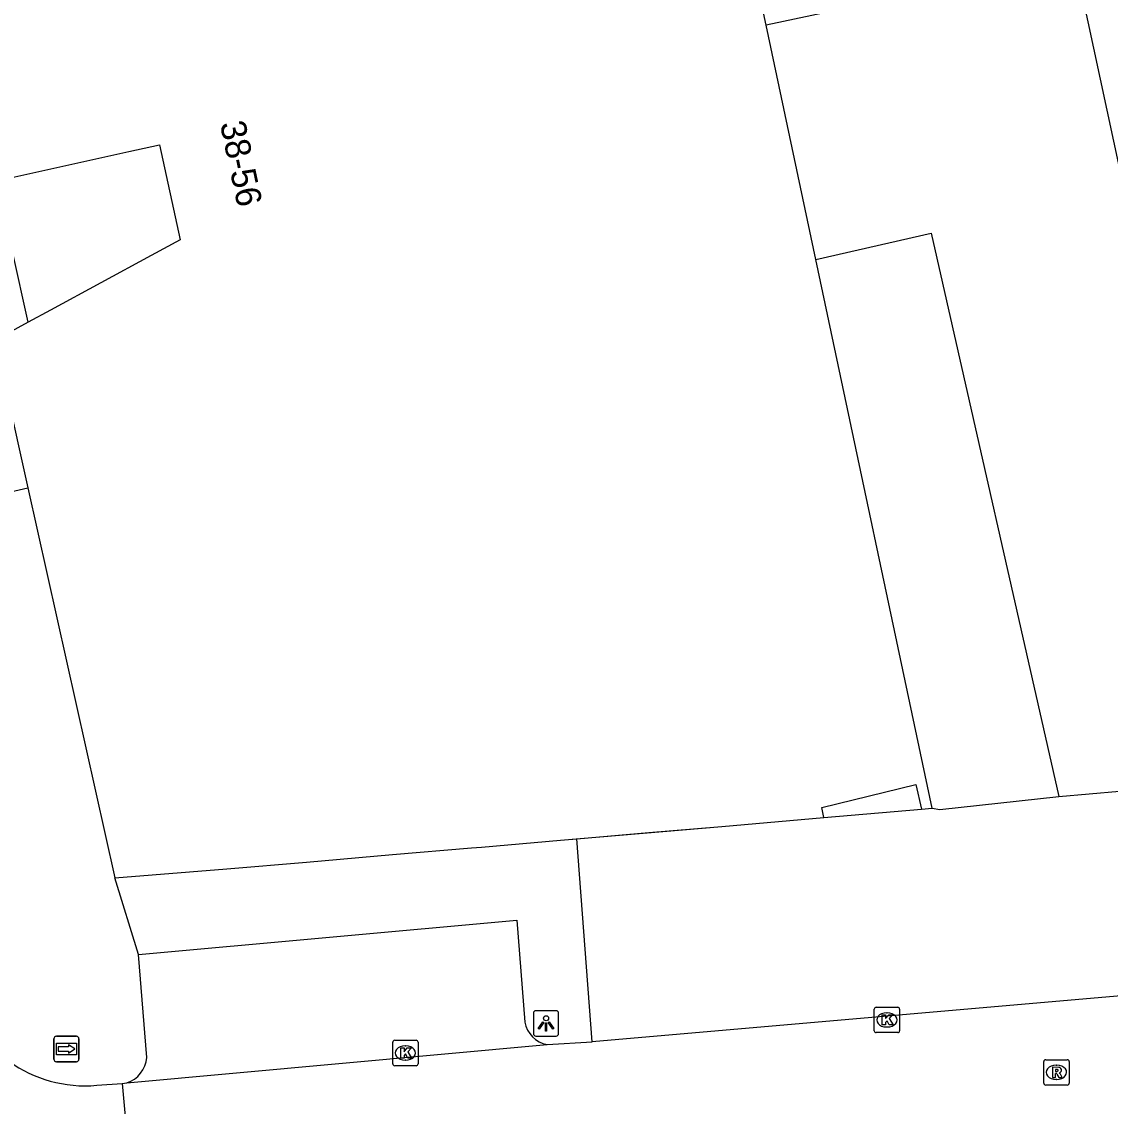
# Model space of a CAD drawing. Extents: x 160557 to 161245, y 385330 to 386505.
# Drawn here: x 160808.55 to 160851.48, y 385607.11 to 385649.87 of the extents above; entities that cross this region are included whole.
import ezdxf

# ---------------------------------------------------------------- set-up
doc = ezdxf.new("R2010")
doc.units = 0
for name, color, linetype in [('IMGEO_Kolk', 7, 'Continuous'), ('IMGEO_Lichtpunt', 7, 'Continuous'), ('IMGEO_Pand', 7, 'Continuous'), ('IMGEO_Pand_nummerreeks', 7, 'Continuous'), ('IMGEO_Pand_overbouw', 7, 'Continuous'), ('IMGEO_Parkeervlak_open', 7, 'Continuous'), ('IMGEO_Rijbaan_lokaal_open', 7, 'Continuous'), ('IMGEO_Rioolput', 7, 'Continuous'), ('IMGEO_Voetpad_gesloten', 7, 'Continuous'), ('IMGEO_Voetpad_open', 7, 'Continuous'), ('IMGEO_Wegwijzer', 7, 'Continuous')]:
    doc.layers.add(name, color=color, linetype=linetype)

msp = doc.modelspace()

# ---------------------------------------------------------------- linework, layer by layer
at = {"layer": 'IMGEO_Kolk'}
for p, q in [((160842.172, 385610.091), (160842.172, 385610.943)), ((160842.247, 385611.017), (160843.099, 385611.017)), ((160842.66, 385610.797), (160842.685, 385610.797)), ((160843.173, 385610.943), (160843.173, 385610.091)), ((160843.099, 385610.017), (160842.247, 385610.017)), ((160842.683, 385610.237), (160842.658, 385610.237)), ((160823.186, 385608.786), (160823.186, 385609.638)), ((160823.261, 385609.712), (160824.113, 385609.712)), ((160823.674, 385609.492), (160823.699, 385609.492)), ((160824.187, 385609.638), (160824.187, 385608.786)), ((160824.113, 385608.712), (160823.261, 385608.712)), ((160823.697, 385608.932), (160823.672, 385608.932))]:
    msp.add_line(p, q, dxfattribs=at)
for points in [[(160842.172, 385610.091), (160842.172, 385610.943)], [(160842.247, 385611.017), (160843.099, 385611.017)], [(160843.173, 385610.943), (160843.173, 385610.091)], [(160842.493, 385610.717), (160842.616, 385610.717), (160842.616, 385610.566), (160842.746, 385610.717), (160842.91, 385610.717), (160842.764, 385610.566), (160842.917, 385610.317), (160842.765, 385610.317), (160842.68, 385610.481), (160842.616, 385610.414), (160842.616, 385610.317), (160842.493, 385610.317), (160842.493, 385610.717)], [(160843.099, 385610.017), (160842.247, 385610.017)], [(160823.186, 385608.786), (160823.186, 385609.638)], [(160823.261, 385609.712), (160824.113, 385609.712)], [(160824.187, 385609.638), (160824.187, 385608.786)], [(160823.507, 385609.412), (160823.63, 385609.412), (160823.63, 385609.261), (160823.76, 385609.412), (160823.924, 385609.412), (160823.778, 385609.261), (160823.931, 385609.012), (160823.779, 385609.012), (160823.694, 385609.176), (160823.63, 385609.109), (160823.63, 385609.012), (160823.507, 385609.012), (160823.507, 385609.412)], [(160824.113, 385608.712), (160823.261, 385608.712)]]:
    msp.add_lwpolyline(points, dxfattribs=at)
for centre, start, end in [((160842.249, 385610.941), 91.552, 178.448), ((160842.249, 385610.941), 91.552, 178.448), ((160843.097, 385610.941), 1.552, 88.448), ((160843.097, 385610.941), 1.552, 88.448), ((160842.249, 385610.093), 181.552, 268.448), ((160842.249, 385610.093), 181.552, 268.448), ((160843.097, 385610.093), 271.552, 358.448), ((160843.097, 385610.093), 271.552, 358.448), ((160823.263, 385609.636), 91.552, 178.448), ((160823.263, 385609.636), 91.552, 178.448), ((160824.111, 385609.636), 1.552, 88.448), ((160824.111, 385609.636), 1.552, 88.448), ((160823.263, 385608.788), 181.552, 268.448), ((160823.263, 385608.788), 181.552, 268.448), ((160824.111, 385608.788), 271.552, 358.448), ((160824.111, 385608.788), 271.552, 358.448)]:
    msp.add_arc(centre, 0.0765, start, end, dxfattribs=at)
for centre, major_axis, ratio, start_param, end_param in [((160842.659, 385610.517), (-0.387, 0.002), 0.722429, 4.712389, 7.853982), ((160842.684, 385610.517), (-0.39, 0.002), 0.717154, 1.570796, 4.712389), ((160823.673, 385609.212), (-0.387, 0.002), 0.722429, 4.712389, 7.853982), ((160823.698, 385609.212), (-0.39, 0.002), 0.717154, 1.570796, 4.712389)]:
    msp.add_ellipse(centre, major_axis=major_axis, ratio=ratio, start_param=start_param, end_param=end_param, dxfattribs=at)
at = {"layer": 'IMGEO_Lichtpunt'}
for p, q in [((160828.732, 385610.783), (160828.732, 385609.976)), ((160828.732, 385610.783), (160828.732, 385609.976)), ((160829.634, 385610.878), (160828.826, 385610.878)), ((160829.634, 385610.878), (160828.826, 385610.878)), ((160829.728, 385609.976), (160829.728, 385610.783)), ((160829.728, 385609.976), (160829.728, 385610.783)), ((160828.826, 385609.882), (160829.634, 385609.882)), ((160828.826, 385609.882), (160829.634, 385609.882))]:
    msp.add_line(p, q, dxfattribs=at)
for points in [[(160829.106, 385610.447), (160829.145, 385610.419), (160828.957, 385610.157), (160828.919, 385610.184), (160829.106, 385610.447)], [(160829.208, 385610.399), (160829.255, 385610.399), (160829.255, 385610.077), (160829.208, 385610.077), (160829.208, 385610.399)], [(160829.318, 385610.419), (160829.356, 385610.446), (160829.543, 385610.184), (160829.504, 385610.156), (160829.318, 385610.419)]]:
    msp.add_lwpolyline(points, dxfattribs=at)
msp.add_circle((160829.231, 385610.581), 0.0994, dxfattribs=at)
for centre, start, end in [((160828.826, 385610.783), 90, 180), ((160828.826, 385610.783), 90, 180), ((160829.634, 385610.783), 0, 90), ((160829.634, 385610.783), 0, 90), ((160828.826, 385609.976), 180, 270), ((160828.826, 385609.976), 180, 270), ((160829.634, 385609.976), 270, 0), ((160829.634, 385609.976), 270, 360)]:
    msp.add_arc(centre, 0.0946, start, end, dxfattribs=at)
at = {"layer": 'IMGEO_Pand'}
for points in [[(160837.913, 385649.731), (160831.957, 385677.464)], [(160882.614, 385635.957), (160878.759, 385636.941), (160867.447, 385640.094), (160867.321, 385639.572), (160859.358, 385637.818), (160858.199, 385643.077), (160852.372, 385641.675), (160850.09, 385652.328), (160837.913, 385649.731)], [(160839.871, 385640.501), (160837.913, 385649.731)], [(160807.556, 385643.592), (160808.287, 385643.755), (160812.781, 385644.753), (160813.993, 385645.022), (160814.797, 385641.265), (160813.659, 385640.65), (160809.682, 385638.499), (160808.802, 385638.023)], [(160844.463, 385618.859), (160839.871, 385640.501)], [(160808.802, 385638.023), (160807.57, 385637.357)], [(160807.57, 385637.357), (160806.691, 385636.881), (160807.944, 385631.298), (160808.794, 385631.497), (160812.22, 385616.114)], [(160840.182, 385618.492), (160840.111, 385618.885), (160843.815, 385619.802), (160844.032, 385618.825)], [(160830.449, 385617.656), (160833.286, 385617.9), (160836.165, 385618.147), (160839.297, 385618.416), (160840.182, 385618.492)], [(160844.032, 385618.825), (160844.463, 385618.859)], [(160812.22, 385616.114), (160816.636, 385616.471), (160819.784, 385616.741), (160823.172, 385617.032), (160826.291, 385617.299), (160826.681, 385617.333), (160829.796, 385617.6), (160830.449, 385617.656)]]:
    msp.add_lwpolyline(points, dxfattribs=at)
at = {"layer": 'IMGEO_Pand_overbouw'}
msp.add_lwpolyline([(160800.168, 385670.228), (160806.16, 385643.282), (160808.794, 385631.497), (160812.22, 385616.114), (160816.636, 385616.471), (160819.784, 385616.741), (160823.172, 385617.032), (160826.291, 385617.299), (160826.681, 385617.333), (160829.796, 385617.6), (160836.165, 385618.147), (160839.297, 385618.416), (160840.182, 385618.492), (160844.032, 385618.825), (160844.463, 385618.859), (160839.871, 385640.501), (160837.913, 385649.731), (160831.957, 385677.464)], dxfattribs=at)
at = {"layer": 'IMGEO_Parkeervlak_open'}
msp.add_lwpolyline([(160839.871, 385640.501), (160844.423, 385641.532), (160849.453, 385619.331)], dxfattribs=at)
at = {"layer": 'IMGEO_Rijbaan_lokaal_open'}
for points in [[(160852.666, 385611.53), (160831.052, 385609.652)], [(160812.695, 385608.034), (160829.274, 385609.552)], [(160829.274, 385609.552), (160831.052, 385609.652)], [(160811.51, 385607.939), (160812.515, 385608.009)], [(160812.515, 385608.009), (160812.695, 385608.034)], [(160812.515, 385608.009), (160812.984, 385602.775)]]:
    msp.add_lwpolyline(points, dxfattribs=at)
msp.add_arc((160811.056, 385613.052), 5.134, 193.7305, 275.0747, dxfattribs=at)
at = {"layer": 'IMGEO_Rioolput'}
for p, q in [((160848.861, 385608.022), (160848.861, 385608.874)), ((160848.936, 385608.948), (160849.788, 385608.948)), ((160849.349, 385608.728), (160849.374, 385608.728)), ((160849.862, 385608.874), (160849.862, 385608.022)), ((160849.788, 385607.948), (160848.936, 385607.948)), ((160849.372, 385608.168), (160849.347, 385608.168))]:
    msp.add_line(p, q, dxfattribs=at)
for points in [[(160848.861, 385608.022), (160848.861, 385608.874)], [(160848.936, 385608.948), (160849.788, 385608.948)], [(160849.45, 385608.646), (160849.198, 385608.648), (160849.198, 385608.248)], [(160849.862, 385608.874), (160849.862, 385608.022)], [(160849.198, 385608.248), (160849.322, 385608.248), (160849.322, 385608.41), (160849.333, 385608.41)], [(160849.376, 385608.567), (160849.322, 385608.567), (160849.322, 385608.486)], [(160849.322, 385608.486), (160849.374, 385608.486)], [(160849.38, 385608.381), (160849.451, 385608.248), (160849.591, 385608.248), (160849.526, 385608.374)], [(160849.788, 385607.948), (160848.936, 385607.948)]]:
    msp.add_lwpolyline(points, dxfattribs=at)
for centre, radius, start, end in [((160848.938, 385608.872), 0.0765, 91.552, 178.448), ((160848.938, 385608.872), 0.0765, 91.552, 178.448), ((160849.449, 385608.536), 0.109, 350.3612, 89.416), ((160849.786, 385608.872), 0.0765, 1.552, 88.448), ((160849.786, 385608.872), 0.0765, 1.552, 88.448), ((160849.332, 385608.357), 0.0533, 26.0293, 88.6989), ((160849.358, 385608.675), 0.19, 274.7715, 282.9687), ((160849.382, 385608.471), 0.0964, 77.0061, 93.1865), ((160849.396, 385608.528), 0.0378, 276.6634, 79.6772), ((160849.447, 385608.536), 0.112, 277.5842, 350.9817), ((160849.431, 385608.321), 0.108, 29.5134, 73.7905), ((160848.938, 385608.024), 0.0765, 181.552, 268.448), ((160848.938, 385608.024), 0.0765, 181.552, 268.448), ((160849.786, 385608.024), 0.0765, 271.552, 358.448), ((160849.786, 385608.024), 0.0765, 271.552, 358.448)]:
    msp.add_arc(centre, radius, start, end, dxfattribs=at)
for centre, major_axis, ratio, start_param, end_param in [((160849.348, 385608.448), (-0.387, 0.002), 0.722429, 4.712389, 7.853982), ((160849.373, 385608.448), (-0.39, 0.002), 0.717154, 1.570796, 4.712389)]:
    msp.add_ellipse(centre, major_axis=major_axis, ratio=ratio, start_param=start_param, end_param=end_param, dxfattribs=at)
at = {"layer": 'IMGEO_Voetpad_gesloten'}
msp.add_lwpolyline([(160808.802, 385638.023), (160807.556, 385643.592)], dxfattribs=at)
at = {"layer": 'IMGEO_Voetpad_open'}
for points in [[(160849.453, 385619.331), (160851.846, 385619.534)], [(160844.463, 385618.859), (160844.766, 385618.807), (160849.453, 385619.331)], [(160840.182, 385618.492), (160844.032, 385618.825)], [(160831.052, 385609.652), (160830.449, 385617.656)], [(160813.155, 385613.096), (160812.22, 385616.114)], [(160813.155, 385613.096), (160828.085, 385614.443), (160828.395, 385610.433)], [(160813.481, 385609.031), (160813.155, 385613.096)]]:
    msp.add_lwpolyline(points, dxfattribs=at)
for centre, radius, start, end in [((160829.449, 385610.605), 1.068, 189.2803, 260.5895), ((160812.352, 385609.113), 1.132, 287.6366, 355.8614)]:
    msp.add_arc(centre, radius, start, end, dxfattribs=at)
at = {"layer": 'IMGEO_Wegwijzer'}
for p, q in [((160809.819, 385608.97), (160809.819, 385609.77)), ((160809.819, 385609.77), (160809.819, 385608.97)), ((160809.919, 385609.87), (160810.709, 385609.87)), ((160810.709, 385609.87), (160809.919, 385609.87)), ((160810.809, 385609.77), (160810.809, 385608.97)), ((160810.809, 385608.97), (160810.809, 385609.77)), ((160810.709, 385608.87), (160809.919, 385608.87)), ((160809.919, 385608.87), (160810.709, 385608.87))]:
    msp.add_line(p, q, dxfattribs=at)
for points in [[(160809.92, 385609.602), (160810.708, 385609.602), (160810.708, 385609.138), (160809.92, 385609.138), (160809.92, 385609.602)], [(160809.985, 385609.454), (160809.985, 385609.37), (160809.985, 385609.286), (160810.396, 385609.286), (160810.396, 385609.203), (160810.643, 385609.37), (160810.396, 385609.537), (160810.396, 385609.454), (160809.985, 385609.454)]]:
    msp.add_lwpolyline(points, dxfattribs=at)
for centre, start, end in [((160809.919, 385609.77), 90, 180), ((160809.919, 385609.77), 90, 180), ((160810.709, 385609.77), 0, 90), ((160810.709, 385609.77), 360, 90), ((160809.919, 385608.97), 180, 270), ((160809.919, 385608.97), 180, 270), ((160810.709, 385608.97), 270, 0), ((160810.709, 385608.97), 270, 0)]:
    msp.add_arc(centre, 0.1, start, end, dxfattribs=at)

# ---------------------------------------------------------------- texts
at = {"layer": 'IMGEO_Pand_nummerreeks'}
msp.add_text('38-56', height=1, rotation=281.9918, dxfattribs=at).set_placement((160816.366, 385645.857))

doc.saveas('drawing.dxf')
